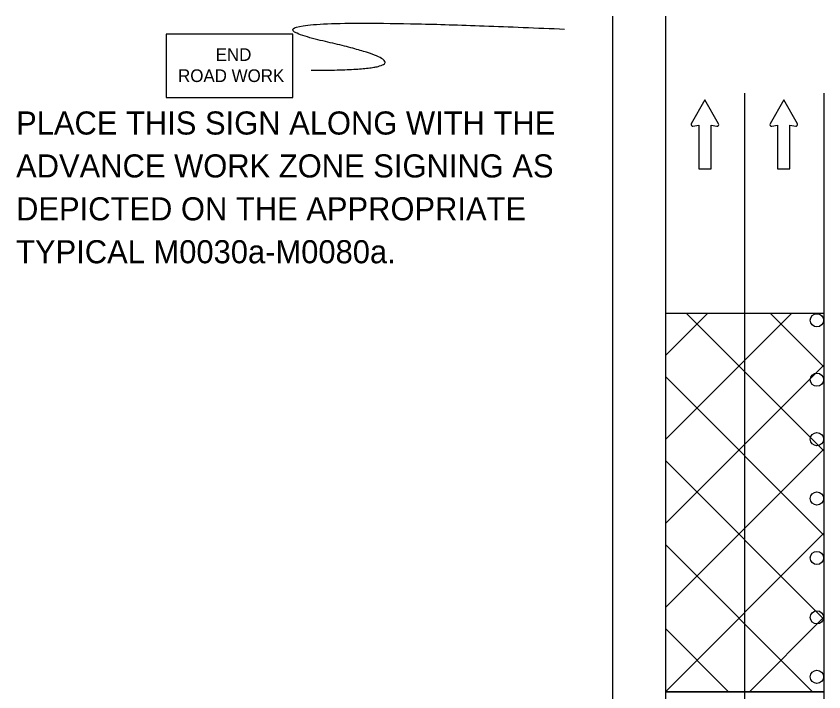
# Model space of a CAD drawing. Extents: x 16794 to 19504, y 7009 to 8243.
# Drawn here: x 17835.7 to 18080.4, y 8010 to 8214.7 of the extents above; entities that cross this region are included whole.
import ezdxf

# ---------------------------------------------------------------- set-up
doc = ezdxf.new("R2010")
doc.units = 0
for name, color, linetype in [('ALI_LEGAL_EX', 7, 'Continuous'), ('MT_SCRATCH_LEVEL_A', 7, 'Continuous'), ('MT_SCRATCH_LEVEL_E', 7, 'Continuous'), ('PAVT_EDGE_EX', 7, 'Continuous'), ('TRAFFIC_SIGNS_PR', 7, 'Continuous')]:
    doc.layers.add(name, color=color, linetype=linetype)

msp = doc.modelspace()

# ---------------------------------------------------------------- linework, layer by layer
at = {"layer": 'ALI_LEGAL_EX'}
for p, q in [((18056.37, 8191.42), (18056.37, 7362.23)), ((18080.37, 8191.42), (18080.37, 7362.23)), ((18080.37, 8191.42), (18080.37, 7362.23))]:
    msp.add_line(p, q, dxfattribs=at)
for points in [[(18056.37, 8191.42), (18056.37, 8166.42)], [(18080.37, 8191.42), (18080.37, 8166.42)], [(18056.37, 8091.42), (18056.37, 8066.42)], [(18080.37, 8091.42), (18080.37, 8066.42)]]:
    msp.add_lwpolyline(points, dxfattribs=at)
at = {"layer": 'MT_SCRATCH_LEVEL_A'}
for p, q in [((18080.37, 8124.58), (18032.37, 8124.58)), ((18080.37, 8010.04), (18032.37, 8010.04))]:
    msp.add_line(p, q, dxfattribs=at)
at = {"layer": 'MT_SCRATCH_LEVEL_E'}
for p, q in [((18044.31, 8189.32), (18040.2, 8182.08)), ((18048.46, 8182.08), (18044.31, 8189.32)), ((18068.21, 8189.32), (18064.1, 8182.08)), ((18072.36, 8182.08), (18068.21, 8189.32)), ((18040.68, 8181.39), (18042.46, 8181.71)), ((18042.46, 8181.71), (18042.46, 8168.45)), ((18046.2, 8168.45), (18046.2, 8181.71)), ((18046.2, 8181.71), (18047.98, 8181.39)), ((18064.58, 8181.39), (18066.36, 8181.71)), ((18066.36, 8181.71), (18066.36, 8168.45)), ((18070.1, 8168.45), (18070.1, 8181.71)), ((18070.1, 8181.71), (18071.88, 8181.39)), ((18042.46, 8168.45), (18046.2, 8168.45)), ((18066.36, 8168.45), (18070.1, 8168.45))]:
    msp.add_line(p, q, dxfattribs=at)
for centre, start, end in [((18040.61, 8181.85), 150.4248, 279.9638), ((18048.05, 8181.85), 260.0362, 29.7731), ((18064.51, 8181.85), 150.4248, 279.9638), ((18071.95, 8181.85), 260.0362, 29.7731)]:
    msp.add_arc(centre, 0.463, start, end, dxfattribs=at)
at = {"layer": 'PAVT_EDGE_EX'}
for p, q in [((18016.37, 8214.7), (18016.37, 7554.34)), ((18032.37, 8214.7), (18032.37, 7554.34)), ((18080.37, 8124.58), (18032.37, 8124.58)), ((18032.37, 8124.58), (18032.37, 8010.04)), ((18032.37, 8111.87), (18045.08, 8124.58)), ((18032.37, 8086.41), (18070.53, 8124.58)), ((18080.37, 8082.96), (18038.74, 8124.58)), ((18080.37, 8108.41), (18064.2, 8124.58)), ((18032.37, 8060.96), (18080.37, 8108.96)), ((18080.37, 8057.5), (18032.37, 8105.5)), ((18032.37, 8035.5), (18080.37, 8083.5)), ((18080.37, 8032.05), (18032.37, 8080.05)), ((18032.37, 8010.04), (18080.37, 8058.04)), ((18076.91, 8010.04), (18032.37, 8054.59)), ((18057.82, 8010.04), (18080.37, 8032.59)), ((18051.46, 8010.04), (18032.37, 8029.14)), ((18032.37, 8010.04), (18080.37, 8010.04)), ((18080.37, 8010.04), (18032.37, 8010.04)), ((18032.37, 8010.04), (18032.37, 7980.62)), ((18032.37, 8010.04), (18032.37, 8010.04))]:
    msp.add_line(p, q, dxfattribs=at)
at = {"layer": 'TRAFFIC_SIGNS_PR'}
msp.add_lwpolyline([(17881.16, 8190.01), (17919.56, 8190.01), (17919.56, 8209.21), (17881.16, 8209.21)], close=True, dxfattribs=at)
for centre in [(18078.27, 8122.56), (18078.27, 8104.56), (18078.27, 8086.56), (18078.27, 8068.56), (18078.27, 8050.56), (18078.27, 8032.56), (18078.27, 8014.56)]:
    msp.add_circle(centre, 2, dxfattribs=at)
msp.add_open_spline([(17925.08, 8198.31), (17967.6, 8198.31), (17891.08, 8215.73), (18001.86, 8210.78)], degree=2, dxfattribs=at)

# ---------------------------------------------------------------- texts
for s, height, p in [('END', 3.831, (17896.16, 8201.14)), ('ROAD WORK', 3.831, (17884.77, 8194.75)), ('PLACE THIS SIGN ALONG WITH THE', 7, (17835.71, 8178.83)), ('ADVANCE WORK ZONE SIGNING AS', 7, (17835.71, 8165.83)), ('DEPICTED ON THE APPROPRIATE', 7, (17835.71, 8152.83)), ('TYPICAL M0030a-M0080a.', 7, (17835.71, 8139.83))]:
    msp.add_text(s, height=height, dxfattribs=at).set_placement(p)

doc.saveas('drawing.dxf')
